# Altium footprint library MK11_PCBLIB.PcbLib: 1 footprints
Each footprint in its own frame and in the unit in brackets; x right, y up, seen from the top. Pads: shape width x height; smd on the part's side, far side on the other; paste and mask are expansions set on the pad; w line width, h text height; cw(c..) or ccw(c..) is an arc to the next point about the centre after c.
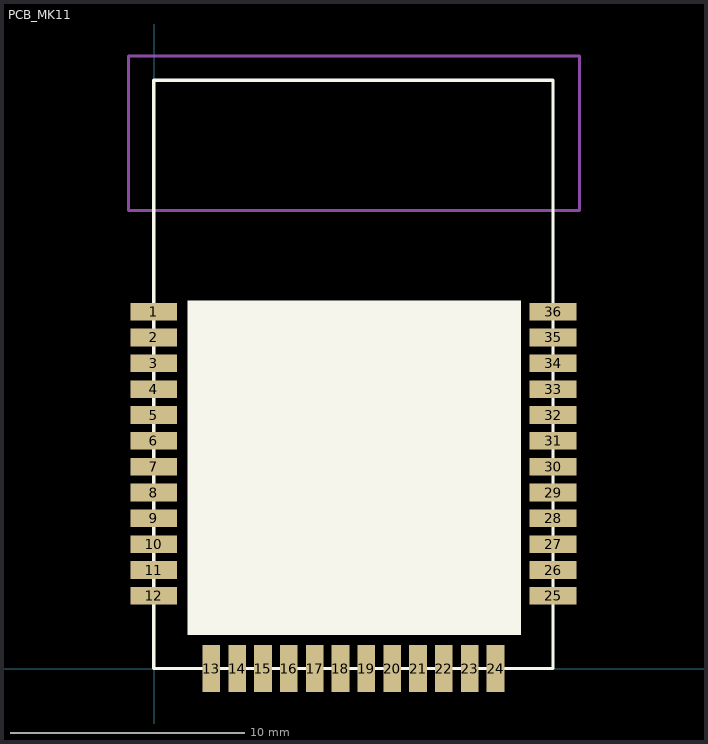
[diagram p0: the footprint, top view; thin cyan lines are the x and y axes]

## PCB_MK11 [mm] "25.05mm*17mm"
height 1.3
pads (36):
  rect 2x0.75 smd: 1(-0.016,15.195) 2(-0.016,14.095) 3(-0.016,12.995) 4(-0.016,11.895) 5(-0.016,10.795) 6(-0.016,9.695) 7(-0.016,8.595) 8(-0.016,7.495) 9(-0.016,6.395) 10(-0.016,5.295) 11(-0.016,4.195) 12(-0.016,3.095) 25(16.984,3.095) 26(16.984,4.195) 27(16.984,5.295) 28(16.984,6.395) 29(16.984,7.495) 30(16.984,8.595) 31(16.984,9.695) 32(16.984,10.795) 33(16.984,11.895) 34(16.984,12.995) 35(16.984,14.095) 36(16.984,15.195)
  rect 0.75x2 smd: 13(2.434,-0.005) 14(3.534,-0.005) 15(4.634,-0.005) 16(5.734,-0.005) 17(6.834,-0.005) 18(7.934,-0.005) 19(9.034,-0.005) 20(10.134,-0.005) 21(11.234,-0.005) 22(12.334,-0.005) 23(13.434,-0.005) 24(14.534,-0.005)
Top Overlay:
  rectangle: 1.422,1.422 15.621,15.672
  lines w0.13: -0.016,-0.005 -0.016,25.045 16.984,25.045 16.984,-0.005 -0.016,-0.005
Mechanical 2:
  lines w0.127: 18.11,19.5 -1.092,19.5 -1.092,26.086 18.11,26.086 18.11,19.507
  text "No ground pad" at 3.277,22.174 h0.8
